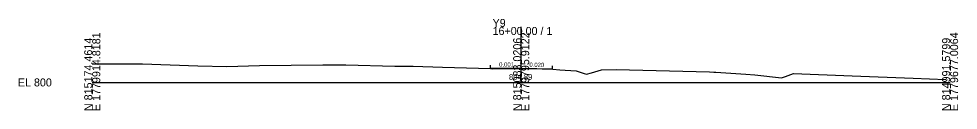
# Model space of a CAD drawing. Extents: x -26 to 1303, y -10 to 9523.
# Drawn here: x 974.3 to 1302.8, y -9.7 to 22.2 of the extents above; entities that cross this region are included whole.
import ezdxf

# ---------------------------------------------------------------- set-up
doc = ezdxf.new("R2010")
doc.units = 0
for name, color, linetype in [('Exist Cross Section Cell', 7, 'Continuous'), ('Exist XS Center Line Elevation Label', 7, 'Continuous'), ('Exist XS Ground Line', 7, 'Continuous'), ('Prop XS Dump Level', 7, 'Continuous'), ('Prop XS EOT Tick Mark', 7, 'Continuous'), ('Prop XS Finish Grade Pavement', 7, 'Continuous'), ('Prop XS SE Text', 7, 'Continuous')]:
    doc.layers.add(name, color=color, linetype=linetype)

msp = doc.modelspace()

# ---------------------------------------------------------------- linework, layer by layer
at = {"layer": 'Exist Cross Section Cell'}
for p, q in [((1150, 0), (1150, 19.37)), ((1000, 0), (1150, 0)), ((1150, 0), (1300, 0))]:
    msp.add_line(p, q, dxfattribs=at)
at = {"layer": 'Exist XS Ground Line'}
for p, q in [((1000, 6.46), (1016.71, 6.45)), ((1016.71, 6.45), (1017.56, 6.44)), ((1017.56, 6.44), (1036.92, 5.79)), ((1036.92, 5.79), (1047.01, 5.61)), ((1047.01, 5.61), (1058.54, 5.87)), ((1058.54, 5.87), (1080.59, 6.19)), ((1080.59, 6.19), (1088.7, 6.14)), ((1088.7, 6.14), (1105.87, 5.69)), ((1105.87, 5.69), (1112.19, 5.66)), ((1112.19, 5.66), (1122.52, 5.33)), ((1122.52, 5.33), (1139.29, 4.87)), ((1139.29, 4.87), (1142.71, 4.88)), ((1142.71, 4.88), (1149.96, 4.89)), ((1149.96, 4.89), (1157.37, 4.74)), ((1157.37, 4.74), (1161.09, 4.67)), ((1161.09, 4.67), (1163.51, 4.42)), ((1163.51, 4.42), (1169.18, 4.05)), ((1169.18, 4.05), (1172.02, 3.07)), ((1172.84, 2.87), (1174.63, 3.3)), ((1174.63, 3.3), (1178.07, 4.36)), ((1178.07, 4.36), (1183.22, 4.53)), ((1183.22, 4.53), (1215.89, 3.68)), ((1215.89, 3.68), (1217.42, 3.62)), ((1217.42, 3.62), (1218.1, 3.59)), ((1218.1, 3.59), (1228.6, 2.88)), ((1172.02, 3.07), (1172.84, 2.87)), ((1228.6, 2.88), (1231.66, 2.63)), ((1231.66, 2.63), (1241.03, 1.66)), ((1241.03, 1.66), (1242.46, 2.12)), ((1242.46, 2.12), (1245.21, 3.08)), ((1245.21, 3.08), (1265.76, 2.32)), ((1265.76, 2.32), (1287.13, 1.54)), ((1287.13, 1.54), (1298.48, 1.07))]:
    msp.add_line(p, q, dxfattribs=at)
at = {"layer": 'Prop XS Dump Level'}
for p, q in [((1139.29, 5), (1150, 5.01)), ((1150, 5.01), (1161, 4.8))]:
    msp.add_line(p, q, dxfattribs=at)
at = {"layer": 'Prop XS EOT Tick Mark'}
for p, q in [((1139.29, 5), (1139.29, 6)), ((1161, 4.8), (1161, 5.8))]:
    msp.add_line(p, q, dxfattribs=at)
at = {"layer": 'Prop XS Finish Grade Pavement'}
for p, q in [((1139.29, 5), (1150, 5.01)), ((1150, 5.01), (1161, 4.8))]:
    msp.add_line(p, q, dxfattribs=at)

# ---------------------------------------------------------------- texts
at = {"layer": 'Exist Cross Section Cell'}
for s, p in [('Y9', (1140, 19.37)), ('16+00.00 / 1', (1140, 16.57)), ('EL 800', (974, -1.4))]:
    msp.add_text(s, height=2.8, dxfattribs=at).set_placement(p)
for s, p in [('E 1779914.8181', (1002.8, -10)), ('E 1779795.9122', (1152.8, -10)), ('E 1779677.0064', (1302.8, -10)), ('N 815174.4614', (1000, -10)), ('N 815083.0206', (1150, -10)), ('N 814991.5799', (1300, -10))]:
    msp.add_text(s, height=2.8, rotation=90, dxfattribs=at).set_placement(p)
at = {"layer": 'Exist XS Center Line Elevation Label'}
msp.add_text('804.89', height=2, dxfattribs=at).set_placement((1145.73, 0.89))
at = {"layer": 'Prop XS Dump Level'}
msp.add_text('Eop', height=0.3, dxfattribs=at).set_placement((1139.29, 4.57))
at = {"layer": 'Prop XS SE Text'}
for s, rotation, p in [('0.001', 0.0688, (1142.3, 5.51)), ('0.020', 358.8771, (1152.87, 5.46))]:
    msp.add_text(s, height=1.5, rotation=rotation, dxfattribs=at).set_placement(p)

doc.saveas('drawing.dxf')
